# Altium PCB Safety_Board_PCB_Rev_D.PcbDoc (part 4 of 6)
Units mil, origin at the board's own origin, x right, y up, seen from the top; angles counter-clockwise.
Board outline 11000 x 4400 mil, 6 copper layers (L1-TOP, L2-Plane, L3-Signal, L4-Signal, L5-Plane, L6-BOT); 712 components, 540 nets, 2214 pads, 875 vias.
Unrouted connection lines stored in the file: 3.
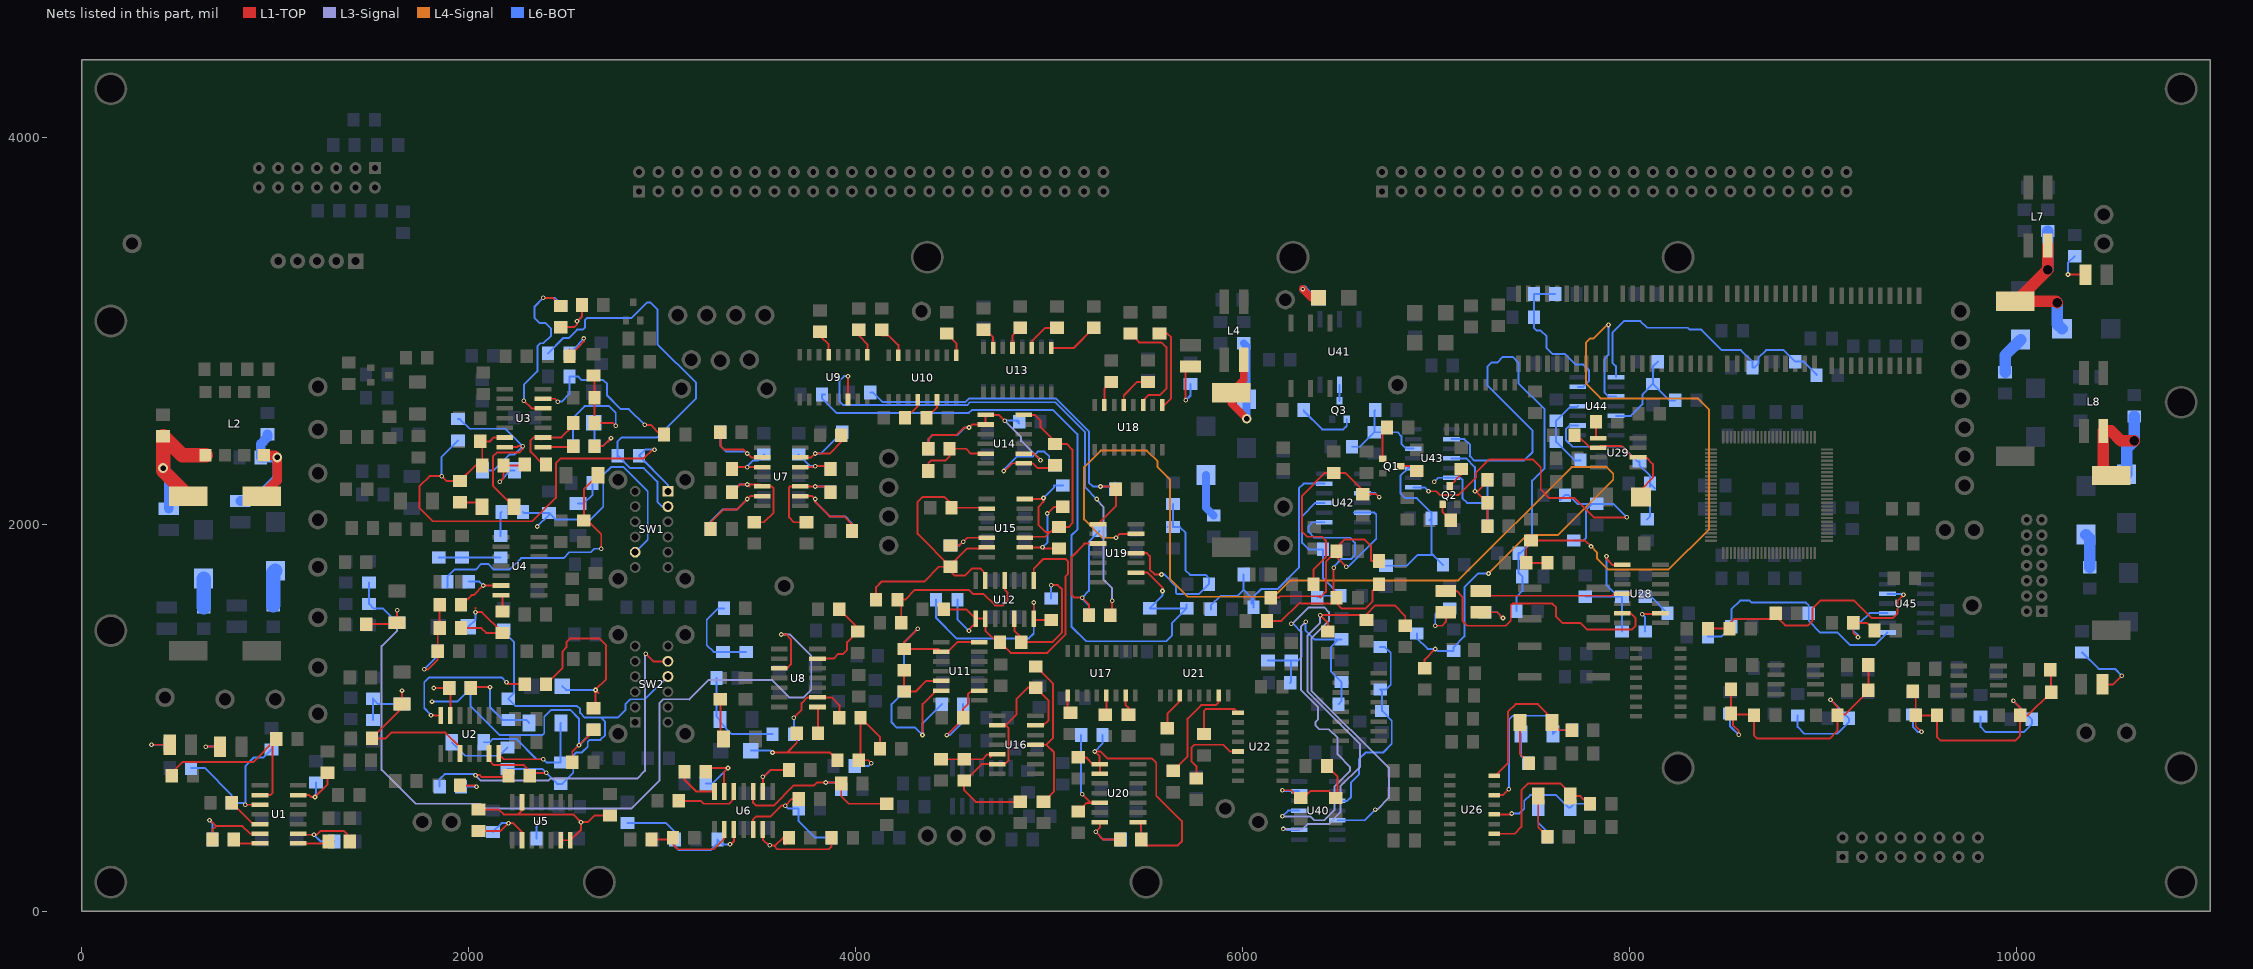
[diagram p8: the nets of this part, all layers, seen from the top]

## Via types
v1: diameter 24, hole 12, L1-TOP to L6-BOT, 720 vias
v2: diameter 50, hole 28, L1-TOP to L6-BOT, 138 vias
v3: diameter 28, hole 50, L1-TOP to L6-BOT, 17 vias

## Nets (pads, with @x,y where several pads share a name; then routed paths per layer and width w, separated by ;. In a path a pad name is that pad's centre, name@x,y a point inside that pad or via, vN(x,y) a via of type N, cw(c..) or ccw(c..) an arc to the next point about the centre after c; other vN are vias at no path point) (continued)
NetC28_2: C28.2 R130.1 R133.1 U40.13 | length 597.8
  L1-TOP w10: v1(6205,625) 6250,625 R130.1@6289.88,585.12 ; R130.1@6300,585.12 6315.12,585.12 6350,620 6445.12,620 R133.1@6480,585.12 6490,595.12 6490,695.12 C28.2@6435.12,750
  L6-BOT w10: v1(6205,625) 6205,630 6215,620 U40.13@6291.57,620
NetC29_2: C29.2 R131.1 R134.1 U42.3 | length 1184.4
  L1-TOP w10: R131.1@6365.12,1690 6365.12,1764.28 6430,1829.16 6430,1915 6410,1935 6334.04,1935 6307,1962.04 6307,2147 6424.88,2264.88 6530.12,2264.88 6620,2175 C29.2@6620,2155.12 6689.88,2155.12 v1(6705,2140)
  L6-BOT w10: U42.3@6618.43,2160 6685,2160 v1(6705,2140)
NetC30_2: C30.2 R126.1 R135.1 U42.5 | length 1446.8
  L1-TOP w10: R126.1@6145.12,1620 6185,1620 6192.66,1627.65 6407.66,1627.65 ; 6400,1620 6430,1650 6430,1805.12 R135.1@6484.88,1860 ; v1(6535,1780) 6484.88,1830.12 6484.88,1879.88 6525,1920 6630,1920 6662.43,1887.57 6662.43,1812.57 6665,1810 C30.2@6704.88,1810
  L6-BOT w10: v1(6535,1780) 6545,1780 6690,1925 6690,2050 6680,2060 6575,2060
NetC31_2: C31.2 R124.1 R136.1 U42.9 | length 1528.8
  L1-TOP w10: R124.1@6125.12,1500 6200,1500 6290,1590 6454.88,1590 R136.1@6484.88,1620 6470,1634.88 v1(6470,1775) ; R136.1@6470,1595 6485,1610 R136.1@6485,1645 ; R136.1@6484.88,1590.12 6510,1565 6635,1565 6670,1600 6670,1655.12 C31.2@6704.88,1690
  L6-BOT w10: U42.9@6421.57,2010 6360,2010 6340,1990 6340,1960 6370,1930 6555,1930 6580,1905 6580,1840 6560,1820 6510,1820 6470,1780 v1(6470,1775)
NetC32_2: C32.2 R137.1 R143.1 U40.9 | length 2301.1
  L1-TOP w10: R137.1@6440,1445.12 6440,1490 v1(6400,1530) 6615.12,1530 R143.1@6640,1505.12 6640,1535 6685,1580 6785,1580 6840,1525 C32.2@6840,1475.12
  L3-Signal w10: v1(6210,425) 6310,425 6335,450 6445,450 6505,510 6505,645 6605,745 6605,865 6335,1135 6335,1425 6400,1490 v1(6400,1530)
  L6-BOT w10: v1(6210,425) 6210,435 6225,420 U40.9@6291.57,420
NetC34_2: C34.2 R157.2 R158.1 U43.11 | length 555.6
  L1-TOP w10: v1(7200,2170) 7204.88,2170 C34.2@7264.88,2110 R158.1@7264.88,1990 ; 7215,2170 7264.88,2219.88 R157.2@7264.88,2230
  L6-BOT w10: U43.11@7078.43,2340 7155,2340 7200,2295 v1(7200,2170)
NetC35_2: C35.2 R156.1 R164.1 U44.3 | length 3423.3
  L1-TOP w10: R164.1@7574.88,1800 R156.1@7465.12,1800 7465.12,1890 C35.2@7490,1914.88 7770.12,1914.88 v1(7800,1885)
  L4-Signal w10: v1(7800,1885) 7830,1855 7830,1825 7890,1765 8200,1765 8410,1975 8410,2590.96 8350.96,2650 7850,2650 7775,2725 7775,2940 7795,2960 7813,2960 v1@7883,3030
  L3-Signal w10: v1@7890,3020 v1(7890,3030)
  L6-BOT w10: v1(7890,3030) 7890,2875 7870,2855 7870,2680 7890,2660 U44.3@7928.43,2660
NetC37_2: C37.2 U29.5 | length 93.4
  L1-TOP w10: C37.2@7824.88,2530 7824.88,2457.76 U29.5@7837.6,2445.04 U29.5@7839.84,2447.28
NetC38_1: C38.1 R162.1 U29.2 U29.6 | length 663
  L1-TOP w10: R162.1@7729.96,2460.04 7794.96,2395.04 U29.6@7837.6,2395.04 ; U29.6@7832.6,2390.04 7847.6,2405.04 7954.96,2405.04 8014.96,2345.04 8084.96,2345.04 8120,2310 8120,2240 8058.43,2178.43 C38.1@8058.43,2140
NetC40_2: C40.2 R170.1 R174.1 U45.5 | length 1404.1
  L1-TOP w10: C40.2@8405.12,1460 R170.1@8514.88,1460 8514.88,1484.88 8540,1510 8724.88,1510 R174.1@8754.88,1540 8754.88,1525.12 8803,1477 8922,1477 8945,1500 8945,1565 8985,1605 9160,1605 9250,1515 9360,1515 9385,1540 9385,1605 v1(9415,1635) v1@9415,1625
  L6-BOT w10: U45.5@9331.57,1640 9410,1640 v1(9415,1635)
NetC41_2: C41.2 C153.2 R171.2 R173.2 R175.2 R177.2 R178.2 R364.2 R369.1 | length 2065.8
  L1-TOP w10: R171.2@8522.85,1146.92 8522.85,1027.15 C41.2@8533.08,1016.92 ; v1(8562.96,911.92) 8562.96,931.92 8533.08,961.8 C41.2@8533.08,1016.92 ; v1(9037.96,1091.92) 9073.08,1056.8 9073.08,932.04 9032.96,891.92 8657.96,891.92 8642.85,907.04 8642.85,1016.92 C41.2@8533.08,1016.92 ; R175.2@9073.08,1016.92 9113.08,1016.92 9233.08,1136.92 R177.2@9233.08,1246.92
  L6-BOT w10: R364.2@8517.96,1021.8 8517.96,956.92 v1(8562.96,911.92) ; R369.1@8867.96,1011.8 8867.96,951.92 8902.96,916.92 9072.96,916.92 9133.08,977.04 C153.2@9133.08,996.92 9132.96,996.92 v1(9037.96,1091.92)
NetC42_2: C42.2 R176.1 R372.1 U45.3 | length 494.1
  L1-TOP w10: v1(9180,1415) 9155.12,1439.88 R176.1@9155.12,1490 9224.88,1490 C42.2@9264.88,1450
  L6-BOT w10: v1(9180,1415) 9180,1425 9155.12,1449.88 R372.1@9155.12,1490 9190,1490 9240,1540 U45.3@9331.57,1540
NetC43_2: C43.2 C160.2 R182.2 R184.2 R185.2 R186.2 R187.2 R378.2 R380.1 | length 2045.1
  L1-TOP w10: R182.2@9462.85,1136.92 9478.08,1121.68 9478.08,956.8 v1(9507.96,926.92) ; C43.2@9478.08,1011.92 R184.2@9587.85,1011.92 9587.85,902.04 9607.96,881.92 9992.96,881.92 10018.08,907.04 10018.08,1051.8 v1(9982.96,1086.92) ; R185.2@10018.08,1011.92 10058.08,1011.92 R187.2@10178.08,1131.92 10178.08,1241.92 R186.2@10173.08,1246.92
  L6-BOT w10: R378.2@9462.96,1016.8 9462.96,951.92 9487.96,926.92 v1(9507.96,926.92) ; R380.1@9812.96,1006.8 9812.96,951.92 9837.96,926.92 10037.96,926.92 10078.08,967.04 C160.2@10078.08,991.92 10077.96,991.92 v1(9982.96,1086.92)
NetC44_2: C44.2 L1.1 L2.1 R1.2 | length 846.7
  L1-TOP w75: L1.1@550,2145 420,2275 R1.2@420,2454.88 518.27,2356.61 L2.1@640,2356.61
  L6-BOT w50: v2(420,2290) 420,2275 450,2245 C44.2@450,2080.12
NetC46_2: C46.2 R190.1 | length 148.9
  L6-BOT w75: R190.1@630,1570.12 C46.2@630,1719.02
NetC47_2: C47.2 R189.2 R196.2 U1.3 | length 828.8
  L1-TOP w10: v1(845,550) U1.3@921.57,550
  L6-BOT w10: R189.2@565.12,740 635,740 775.12,599.88 C47.2@775.12,560 835,560 v1(845,550) 845,750 890,795 940.12,795 R196.2@980,834.88 R196.2@979.88,834.88
NetC48_2: C48.2 L2.4 L3.1 R193.2 R194.2 | length 888.9
  L1-TOP w50: L3.1@930,2145 1010,2225 v2(1010,2345) 998.39,2356.61 L2.4@940,2356.61
  L1-TOP w60: L3.1@930,2145 L3.1@940,2155
  L6-BOT w50: C48.2@820,2120.12 895.12,2120.12 1010,2235 v2(1010,2345) R193.2@925.12,2345 925.12,2415.12 960,2450 R194.2@960,2464.88
NetC50_1: C50.1 R195.1 | length 183
  L6-BOT w75: R195.1@990,1580.12 990,1749.02 C50.1@1000,1759.02
NetC61_2: C61.2 D3.K D15.A R14.2 R206.2 U8.3 | length 4962.2
  L1-TOP w10: R14.2@1469.76,1483.11 1622.32,1483.11 D3.K@1629.65,1490.43 1629.65,1554.65 v1(1630,1555) ; U8.3@3605,1255 3645,1255 3665,1275 3665,1405 3640,1430 v1(3615,1430)
  L3-Signal w7: 3005,1095 3140,1095
  L3-Signal w10: v1(1630,1555) 1630,1450 1550,1370 1550,730 1725,555 2060,555 2085,530 2840,530 2985,675 2985,1075 3005,1095 ; 3140,1095 3240,1195 3565,1195 3655,1105 3730,1105 3770,1145 3770,1320 3660,1430 v1(3615,1430)
  L6-BOT w10: R206.2@1484.65,1697.99 C61.2@1484.65,1588.23 1509.76,1563.11 1556.97,1563.11 D15.A@1629.65,1490.43 ; D15.A@1629.65,1474.65 D15.A@1629.65,1490.43 ; v1(1630,1555) 1630,1490.79 D15.A@1629.65,1490.43
NetC62_2: C62.2 D5.K D18.A R16.2 R209.1 U2.3 | length 1213.9
  L1-TOP w10: v1(1655,1140) 1654.65,1139.65 1654.65,1047.99 R16.2@1499.76,893.11 1569.65,893.11 1599.65,923.11 1879.65,923.11 1954.65,848.11 U2.3@1954.65,784.69
  L6-BOT w10: R209.1@1504.65,988.23 C62.2@1504.65,1097.99 1532.2,1070.43 D18.A@1654.65,1070.43 1655,1070.79 v1(1655,1140)
NetC63_1: C63.1 R25.2 | length 167.3
  L1-TOP w10: R25.2@1955.12,650 2032.76,650 v1(2039.65,643.11)
  L6-BOT w10: C63.1@1959.76,643.11 v1(2039.65,643.11)
NetC63_2: C63.2 R29.1 SW2.11 | length 2030.4
  L1-TOP w10: v1(2034.65,703.11) 2056.89,703.11 2067.59,692.41 2167.29,692.41 R29.1@2174.88,700 ; v1(2915,1330) 2953.78,1291.22 SW2.11@3029.29,1291.22
  L3-Signal w10: v1(2034.65,703.11) 2062.76,675 2411.66,675 2421.66,685 2870,685 2910,725 2910,1325 v1(2915,1330)
  L6-BOT w10: C63.2@1849.53,643.11 1849.53,682.99 1874.65,708.11 2029.65,708.11 v1(2034.65,703.11)
NetC64_1: C64.1 R19.2 R20.1 R21.1 R235.2 SW1.1 U3.6 | length 2824.6
  L1-TOP w10: U3.6@2186.22,2448.11 2129.65,2448.11 2109.65,2428.11 R19.2@2059.76,2428.11 2069.53,2418.35 R20.1@2069.53,2303.11 2034.53,2303.11 R21.1@1954.65,2223.23 1884.53,2223.23 v1(1859.65,2248.11) 1798.11,2248.11 1745,2195 1745,2085 1815,2015 2329.23,2015 2450,2135.77 2450,2315 2475,2340 2905,2340 2950,2385 v1(2960,2385)
  L6-BOT w10: v1(1859.65,2248.11) 1859.65,2347.99 C64.1@1944.65,2432.99 ; v1(2960,2385) 2911.65,2385 R235.2@2879.76,2353.11 3029.29,2203.58 SW1.1@3029.29,2169.96
NetC64_2: C64.2 D6.K D21.A U3.7 | length 1237.1
  L1-TOP w10: U3.7@2186.22,2398.11 2249.65,2398.11 2254.65,2403.11 v1(2279.65,2403.11) 2279.65,2389.65 2260,2370 2145,2370 2125,2350 2125,2197.68 D6.K@2232.68,2090
  L6-BOT w10: C64.2@1944.65,2543.23 1954.53,2543.23 2004.65,2493.11 2189.65,2493.11 v1(2279.65,2403.11) 2237.32,2360.79 2210.79,2360.79 2128.11,2278.11 D21.A@2071.97,2278.11
NetC65_1: C65.1 R222.2 | length 126.9
  L6-BOT w10: R222.2@2164.65,1938.23 2164.65,2058.23 C65.1@2169.53,2063.11
NetC65_2: C65.2 R228.1 SW1.11 | length 1357.9
  L6-BOT w10: C65.2@2279.76,2063.11 2284.88,2057.99 R228.1@2414.65,2057.99 ; v1(2354.65,1988.11) 2414.65,2048.11 R228.1@2414.65,2057.99 ; SW1.11@2860,1855 2925,1920 2925,2170 2800,2295 2735,2295 2695,2255 2695,2090 2630,2025 2447.64,2025 R228.1@2414.65,2057.99
NetC66_2: C66.2 R211.2 R222.1 | length 320
  L6-BOT w10: R211.2@1844.65,1827.99 R222.1@2164.65,1827.99
NetC69_1: C69.1 R34.2 | length 286.3
  L1-TOP w10: R34.2@2519.76,2903.23 R34.2@2519.76,2868.11 2570,2918.35 2570,2920 2595,2945 v1(2595,2960)
  L6-BOT w10: C69.1@2519.76,2903.23 C69.1@2519.76,2883.11 2570,2933.35 2570,2935 v1(2595,2960)
NetC69_2: C69.2 R235.1 SW1.2 | length 2271.7
  L6-BOT w10: C69.2@2409.53,2883.11 2489.53,2963.11 2518.11,2963.11 2560,3005 2590,3005 2600,3015 2600,3055 2610,3065 2840,3065 2920,3145 2940,3145 2975,3110 2975,2930 3175,2730 3175,2650 2973.11,2448.11 2789.65,2448.11 2769.53,2427.99 R235.1@2769.53,2338.23 ; R235.1@2769.53,2353.11 2771.89,2353.11 2835,2290 2905,2290 2975,2220 2975,2115 2998.78,2091.22 SW1.2@3029.29,2091.22
NetC73_1: C73.1 R29.2 R220.1 R223.1 R224.1 SW2.10 U2.6 | length 2563.3
  L1-TOP w10: U2.6@2104.65,814.69 2104.65,780.35 2130,755 2285,755 2315.12,724.88 R29.2@2315.12,700 2330.12,715 v1(2400,715)
  L6-BOT w7: 2835,1095 2910,1095
  L6-BOT w10: R220.1@2180,1454.88 2180,1445 2232.65,1392.35 2232.65,1126.23 R223.1@2204.65,1098.23 2242.87,1060 2560,1060 2575,1045 2575,1025 2600,1000 2770,1000 2810.85,1040.85 2810.85,1070.85 2835,1095 ; R224.1@2200,734.88 2380.12,734.88 2457.01,657.99 2482.99,657.99 2540,715 2540,805 2555,820 2585,820 2615,850 2615,875 2625,885 2680,885 2705,910 2705,980 2685,1000 ; 2910,1095 3027.48,1212.48 SW2.10@3029.29,1212.48
NetC73_2: C73.2 D20.A D23.K U2.7 | length 905.9
  L1-TOP w10: U2.7@2154.65,814.69 2154.65,810.35 2180,785 v1(2385,785)
  L6-BOT w10: D20.A@2077.32,873.11 2108.11,873.11 2125,890 2245,890 2350,785 v1(2385,785) 2401.77,768.23 C73.2@2474.65,768.23 2474.65,970.43 D23.K@2477.32,973.11
NetC78_2: C78.2 R237.2 R239.2 U6.3 | length 764.4
  L1-TOP w10: v1(3350,345) 3355,345 3370,360 U6.3@3370,421.57
  L6-BOT w10: R237.2@2820,454.88 3020.12,454.88 3065.12,409.88 3065.12,334.88 3085,315 3250,315 3285.12,350.12 C78.2@3285.12,370 3310.12,345 v1(3350,345)
NetC79_2: C79.2 R54.2 R247.2 U7.3 | length 359.4
  L1-TOP w10: R54.2@3360.12,2285 3370.12,2295 v1(3440,2295) U7.3@3516.57,2295
  L6-BOT w10: C79.2@3360.12,2285 3370.12,2295 v1(3440,2295) 3440,2300 3470,2330 3495.12,2330 R247.2@3525,2359.88
NetC80_2: C80.2 R55.2 R58.2 U7.5 | length 596
  L1-TOP w10: R55.2@3360.12,2165 3400.12,2205 3506.57,2205 U7.5@3516.57,2195 3565,2195 3575,2185 3575,2060 3525.12,2010.12 R58.2@3475,2010.12 ; v1(3440,2205) 3450,2195
  L6-BOT w10: C80.2@3360.12,2165 3400.12,2205 v1(3440,2205)
NetC82_2: C82.2 R245.1 R246.2 | length 461.1
  L6-BOT w10: R245.1@3318.31,1565 3290,1565 3230,1505 3230,1375 3265.12,1339.88 C82.2@3433.43,1339.88
NetC86_2: C86.2 R63.2 R252.2 U6.5 | length 678
  L1-TOP w10: U6.5@3470,421.57 3470,475 3485,490 3560,490 3615,545 v1(3635,545) 3670,580 R63.2@3704.88,580
  L6-BOT w10: v1(3635,545) 3650,530 C86.2@3704.88,530 3704.88,465.12 3790,380 R252.2@3874.88,380
NetC88_2: C88.2 R67.2 R248.2 U7.12 | length 360.6
  L1-TOP w10: U7.12@3713.43,2295 3785,2295 v1(3790,2300) 3850,2300 3865,2285 R67.2@3869.88,2285
  L6-BOT w10: R248.2@3705,2359.88 3764.88,2300 3854.88,2300 C88.2@3869.88,2285
NetC89_2: C89.2 R61.2 R68.2 U7.10 | length 577
  L1-TOP w10: R61.2@3745,2010.12 3679.88,2010.12 3655,2035 3655,2190 3660,2195 v1(3790,2195) 3839.88,2195 R68.2@3869.88,2165
  L6-BOT w10: v1(3790,2195) 3839.88,2195 C89.2@3869.88,2165
NetC90_2: C90.2 R76.2 R81.2 U6.10 | length 982.2
  L1-TOP w10: U6.10@3470,618.43 3470,560 3485,545 3575,545 3680,650 3785,650 3800,665 3919.88,665 R76.2@3924.88,660 3924.88,595.12 3964.88,555.12 R81.2@4160,555.12
  L6-BOT w10: v1(3845,665) 3889.88,665 C90.2@3924.88,630
NetC104_2: C104.2 R113.1 R261.1 U19.1 | length 1981.9
  L1-TOP w10: U19.1@5251.57,2000 5344.88,2093.31 R113.1@5344.88,2180 5329.88,2195 v1(5265,2195)
  L6-BOT w10: R261.1@4075.12,2680 4090,2680 4138,2632 4567.96,2632 4585.96,2650 5035,2650 5035,2649.04 5205,2479.04 5205,2215 5225,2195 5325,2195 C104.2@5340,2180 C104.2@5340,2215
NetC105_2: C105.2 R109.1 R287.1 U19.3 | length 1015.9
  L1-TOP w10: R109.1@5204.88,1530 5204.88,1585.12 v1(5170,1620) 5130,1620 5115,1635 5115,1830 5180,1895 5180,1900 U19.3@5251.57,1900
  L6-BOT w10: R287.1@5204.88,1530 5204.88,1580.12 5170,1615 v1(5170,1620) 5204.88,1654.88 5204.88,1909.88 C105.2@5260,1965
NetC108_2: C108.2 R298.1 R300.1 U19.11 | length 1104.9
  L1-TOP w10: U19.11@5448.43,1850 5505,1850 5520,1835 5520,1765 5545,1740 v1(5580,1740)
  L6-BOT w10: v1(5580,1740) 5595,1740 5655,1680 5655,1645 5660,1640 5775,1640 5825,1690 R300.1@5825.12,1690 5825.12,1719.88 5807.57,1737.43 5727.57,1737.43 5705,1760 5705,1955 5674.88,1985.12 C108.2@5640,1985.12 R298.1@5640,2104.88 ; C108.2@5610,1985 C108.2@5610,1985.12
NetC109_2: C109.2 R250.1 R295.1 U19.9 | length 3706.2
  L1-TOP w10: U19.9@5448.43,1750 5508,1750 5585,1673 v1(5585,1655)
  L6-BOT w10: R250.1@3840,2670 R250.1@3825.12,2670 3825.12,2649.88 3900,2575 4585,2575 4600,2590 5020,2590 5145,2465 5145,1971.66 5115,1941.66 5115,1470 5190,1395 5605,1395 5635,1425 5635,1490.12 C109.2@5710,1565.12 ; v1@5590,1650 v1(5585,1655) 5585,1630.12 R295.1@5520,1565.12 C109.2@5710,1565.12 ; C109.2@5710,1585 C109.2@5710,1565.12
NetC110_1: C110.1 R302.1 | length 225.5
  L6-BOT w40: C110.1@5810,2254.02 5810,2085.12 R302.1@5850,2045.12
NetC113_1: C113.1 L4.4 L5.1 R307.2 | length 761.2
  L1-TOP w40: L4.4@6005,2850 6005,2745 L5.1@5940,2680 5940,2625 v2(6020,2545)
  L6-BOT w40: R307.2@6005,2934.88 6020,2919.88 v2(6020,2545)
NetC114_2: C114.2 R303.1 R308.1 U42.13 | length 1293.8
  L6-BOT w10: R303.1@5834.88,1560 5834.88,1579.88 5885.12,1630.12 5974.88,1630.12 6004.88,1660.12 ; R308.1@6004.88,1740 6004.88,1660.12 ; C114.2@6045,1590 6045,1620 6004.88,1660.12 ; C114.2@6054.88,1570 6054.88,1624.88 6095,1665 6180,1665 6290,1775 6290,2185 6315,2210 U42.13@6421.57,2210
NetC115_2: C115.2 R309.1 R312.1 U40.5 | length 2228.7
  L3-Signal w10: v1(6250,1485) 6250,1480 6340,1570 6420,1570 6445,1545 6445,1500 6355,1410 6355,1140 6755,740 6755,585 6695,525 v1(6685,525)
  L6-BOT w10: C115.2@6130,1294.88 6284.88,1294.88 6305,1315 6305,1440 6260,1485 v1(6250,1485) ; R309.1@6245.12,1180 6250,1184.88 R312.1@6250,1294.88 ; 6300,1445 6305,1445 ; U40.5@6488.43,470 6630,470 v1(6685,525)
NetC117_2: C117.2 R314.1 R316.1 U42.11 | length 804.5
  L6-BOT w10: C117.2@6385.12,1620 6395.12,1630 R316.1@6504.88,1630 6414.88,1720 R314.1@6414.88,1870 6340,1870 6307,1903 6307,2042 6375,2110 U42.11@6421.57,2110
NetC119_2: C119.2 R313.1 R317.1 U40.11 | length 2189.9
  L3-Signal w10: v1(6205,490) 6350,490 6370,470 6420,470 6475,525 6475,645 6555,725 6555,745 6490,810 6490,895 6445,940 6395,940 6375,960 6375,977 6390,992 6390,1055 6300,1145 6300,1470 v1(6325,1495)
  L6-BOT w10: v1(6205,490) 6235,520 U40.11@6291.57,520 ; v1(6325,1495) 6325,1450 6370.12,1404.88 R317.1@6510,1404.88 ; R317.1@6494.88,1404.88 6455,1365 6455,1239.88 C119.2@6510,1184.88 6510,1084.88 R313.1@6495.12,1070
NetC121_2: C121.2 R315.1 R322.1 U43.5 | length 523.2
  L6-BOT w10: R315.1@6565.12,2400 6604.88,2400 R322.1@6680,2475.12 ; C121.2@6684.88,2590 6680,2585.12 R322.1@6680,2475.12 ; U43.5@6881.57,2390 6845,2390 6820,2415 6820,2455 6799.88,2475.12 R322.1@6680,2475.12
NetC122_2: C122.2 R324.1 R325.1 U40.3 | length 1097.1
  L6-BOT w10: U40.3@6488.43,570 6540,570 6560,590 6560,665 6601.87,706.87 6601.87,786.87 6635,820 6725,820 6770,865 6770,985 6720,1035 6720,1134.88 C122.2@6710,1144.88 6739.88,1144.88 6765,1170 6765,1335 6735.12,1364.88 R324.1@6710,1364.88
NetC124_2: C124.2 R323.1 R326.1 U43.3 | length 951.1
  L6-BOT w10: R323.1@6740,1785.12 6848,1785.12 6902.88,1840 6984.88,1840 ; U43.3@6881.57,2290 6855,2290 6815,2250 6815,2160 6840,2135 6900,2135 6975.12,2059.88 6975.12,1849.76 C124.2@7034.88,1790 ; R326.1@6965.12,2020 R326.1@6975.12,2030
NetC125_2: C125.2 R147.1 R328.1 U19.13 | length 6027.6
  L1-TOP w10: v1(5345,1930) 5365,1950 U19.13@5448.43,1950 ; R147.1@6940,1255.12 6940,1300 v1(6995,1355)
  L4-Signal w10: v1(5345,1930) 5275,1930 5180,2025 5180,2295 5265,2380 5505,2380 5560,2325 5560,2295 5623,2232 5623,1717 5715,1625 6160.96,1625 6245.96,1710 7115,1710 7700,2295 7880,2295 7915,2260 7915,2230 7630,1945 7470,1945 v1(7270,1745)
  L6-BOT w10: R328.1@6900,1434.88 6900,1410 6955,1355 v1(6995,1355) 7005.12,1344.88 C125.2@7090,1344.88 7090,1365 7145,1420 7145,1675 7215,1745 v1(7270,1745)
NetC126_2: C126.2 R339.2 R340.1 U43.13 | length 659.2
  L6-BOT w10: v1(6990,2220) 7010,2240 U43.13@7078.43,2240 ; U43.13@7105,2240 U43.13@7078.43,2240 ; R340.1@7264.88,1990 R339.2@7264.88,2230 ; C126.2@7264.88,2110 7160,2110 7135,2135 7135,2230 7125,2240 U43.13@7078.43,2240
NetC127_2: C127.2 R341.1 R342.1 U43.9 | length 2673
  L6-BOT w10: U43.9@7078.43,2440 7145,2440 7175,2410 7175,2350 7195,2330 7455,2330 7498,2373 7498,2482.96 7265,2715.96 7265,2815 7285,2835 7315,2835 7345,2865 7395,2865 7425,2835 7425,2729.04 7560,2594.04 7560,2290 7495,2225 7495,1909.88 7435.12,1850 R341.1@7425.12,1850 7425.12,1749.76 R342.1@7444.88,1730 7444.88,1654.88 7414.88,1624.88 C127.2@7414.88,1550
NetC129_2: C129.2 R337.1 R338.1 U44.13 | length 821.9
  L6-BOT w10: C129.2@7614.88,3190 R337.1@7505.12,3190 7505.04,3070 7505,3015 7520,3000 7540,3000 7570,2970 7570,2910 7600,2880 7665,2880 7720,2825 7760,2825 7790,2795 7790,2740 7760,2710 U44.13@7731.57,2710
NetC130_2: C130.2 R347.1 R354.1 U43.1 | length 2065
  L1-TOP w10: v1(6960,2170) 7000,2170 7020,2150 7115,2150 7205,2240 7205,2265 7275,2335 7500,2335 7540,2295 7540,2180 7585,2135 7715,2135 7815,2035 v1(7985,2035)
  L6-BOT w10: U43.1@6881.57,2190 6940,2190 v1(6960,2170) ; C130.2@7640,2124.88 C130.2@7665.12,2150 7685,2150 7729.88,2105.12 7914.88,2105.12 v1(7985,2035) ; R347.1@7709.88,1915 R347.1@7710,1914.88 7759.88,1914.88 7775,1930 7775,2075 R354.1@7805.12,2105.12
NetC131_2: C131.2 R355.1 R356.1 U28.1 | length 713.8
  L1-TOP w10: v1(7880,1835) 7880,1820 7910,1790 U28.1@7961.57,1790
  L6-BOT w10: C131.2@7770,1624.88 R355.1@7960,1624.88 R356.1@7960,1445.12 ; v1(7880,1835) 7880,1685 R355.1@7940.12,1624.88
NetC132_2: C132.2 R345.1 R346.1 U44.11 | length 416.7
  L6-BOT w10: U44.11@7731.57,2610 7726.46,2604.88 7690,2604.88 R345.1@7620,2534.88 R346.1@7620,2425.12 7715.12,2330 C132.2@7744.88,2330
NetC133_2: C133.2 R357.1 R358.1 U44.9 | length 914.5
  L6-BOT w10: U44.9@7731.57,2510 7690,2510 7670,2490 7670,2435 7705,2400 7965,2400 8040.12,2324.88 R357.1@8050,2324.88 8050,2305 8105.12,2249.88 8105.12,2040.24 R358.1@8090,2025.12 ; C133.2@8105.12,2210 C133.2@8130,2185.12
NetC135_2: C135.2 R359.1 R360.1 U44.5 | length 565.3
  L6-BOT w10: U44.5@7928.43,2560 8005.96,2560 8065,2619.04 8065,2670.12 R360.1@8120,2725.12 ; R359.1@8145.12,2840 8120,2814.88 R360.1@8120,2725.12 ; C135.2@8234.88,2640 8205.12,2640 R360.1@8120,2725.12
NetC136_2: C136.2 R361.1 R362.1 U28.9 | length 473.6
  L1-TOP w10: v1(8065,1535) 8153.43,1535 U28.9@8158.43,1540
  L6-BOT w10: R362.1@8080,1445.12 8080,1520 v1(8065,1535) 8189.88,1535 C136.2@8194.88,1540 8110,1624.88 R361.1@8080,1624.88
NetC141_2: C141.2 R365.1 R368.1 U45.1 | length 1224.8
  L6-BOT w10: C141.2@8405.12,1420 8474.88,1420 R365.1@8524.88,1470 8524.88,1559.88 8570,1605 8620,1605 8630,1595 8910,1595 8925.12,1579.88 8925.12,1499.88 8985,1440 9075,1440 9140,1375 9266.57,1375 U45.1@9331.57,1440
NetC144_2: C144.2 R367.1 R371.1 U44.1 | length 1546
  L6-BOT w10: U44.1@7928.43,2760 7928.43,2816.57 7910,2835 7910,2990 7970,3050 8055,3050 8090,3015 8300,3015 8310,3005 8370,3005 8475,2900 8575,2900 8635.12,2839.88 C144.2@8635.12,2810 8645,2810 8665,2830 8665,2860 8705,2900 8795.12,2900 R367.1@8855.12,2840 8900,2840 8964.88,2775.12 R371.1@8964.88,2770
NetC157_1: C157.1 R382.1 | length 202
  L6-BOT w60: R382.1@9940,2785.12 9940,2874.02 C157.1@10020,2954.02
NetC161_1: C161.1 L6.1 L7.4 R386.2 | length 920.4
  L1-TOP w60: L6.1@9992.96,3151.92 10203.08,3151.92 v3(10210,3145) ; L6.1@9996.92,3151.92 v3(10160,3315) L7.4@10160,3440
  L6-BOT w60: v3(10160,3315) R386.2@10160,3514.88 ; v3(10210,3145) 10210,3034.02 C161.1@10234.02,3010
NetC163_1: C163.1 R389.1 | length 177.2
  L6-BOT w60: C163.1@10357.96,1945.93 10377.96,1925.93 R389.1@10377.96,1777.04
NetC164_1: C164.1 L8.4 L9.1 R391.2 | length 742.7
  L1-TOP w60: L9.1@10487.96,2251.92 10447.96,2291.92 L8.4@10447.96,2481.92 10487.96,2481.92 10537.96,2431.92 v3(10607.96,2431.92)
  L6-BOT w60: C164.1@10567.96,2257.9 10567.96,2391.92 v3(10607.96,2431.92) R391.2@10607.96,2556.8
NetD6_A: D6.A R21.2 | length 122.2
  L1-TOP w10: R21.2@1954.65,2112.99 2044.33,2112.99 D6.A@2067.32,2090
NetD7_A: D7.A R41.2 R214.1 | length 1394.8
  L1-TOP w10: D7.A@2667.32,2253.11 2594.65,2180.43 R41.2@2594.65,2018.23 2614.53,2018.23 2684.65,1948.11 v1(2684.65,1873.11)
  L6-BOT w10: R214.1@1889.53,1673.23 1889.53,1729.53 1925,1765 2035,1765 2065,1795 2100,1795 2130,1765 2210,1765 2270,1825 2490,1825 2520,1855 2630,1855 2648.11,1873.11 v1(2684.65,1873.11)
NetD9_A: D9.A R52.2 | length 212.1
  L1-TOP w10: R52.2@3300,1094.88 3300,907.32 D9.A@3317.32,890
NetD10_K: D10.K D28.A | length 200.3
  L1-TOP w40: v1(6310,3215) 6355,3170 D10.K@6391.5,3170
  L6-BOT w40: v1(6310,3215) 6315,3215 6360,3170 D28.A@6391.5,3170
NetD13_A: D13.A R165.2 U26.8 | length 777.2
  L1-TOP w10: U26.8@7300.16,700 7305,700 7370,765 7370,1030 7410,1070 7525,1070 7597.68,997.32 D13.A@7597.68,975 7637.68,935 R165.2@7699.88,935
NetD13_K: D13.K R159.1 | length 229.7
  L1-TOP w10: D13.K@7432.32,975 7432.32,812.68 7479.88,765.12 R159.1@7479.88,765
NetD14_A: D14.A R167.2 U26.2 | length 764.4
  L1-TOP w10: U26.2@7300.16,400 7405,400 7440,435 7440,625 7475,660 7640,660 7692.68,607.32 D14.A@7692.68,595 7745,595 7785,555 R167.2@7794.88,555
NetD14_K: D14.K R160.1 | length 229.7
  L1-TOP w10: D14.K@7527.32,595 7527.32,432.56 R160.1@7574.88,385
NetD19_K: D19.K R22.2 R28.2 | length 504.4
  L1-TOP w10: R22.2@1959.76,1463.11 2064.65,1463.11 2089.76,1437.99 R28.2@2174.65,1437.99 2067.64,1545 v1(2035,1545) ; 2034.65,1563.11 2034.65,1568.11
  L6-BOT w10: D19.K@1998.5,1470 2035,1506.5 v1(2035,1545)
NetD20_K: D20.K R224.2 | length 334.4
  L6-BOT w10: D20.K@1911.97,873.11 1981.97,803.11 2157.99,803.11 R224.2@2200,845.12
NetD21_K: D21.K R20.2 R30.1 | length 304.5
  L1-TOP w10: v1(2160,2220) 2179.76,2239.76 R20.2@2179.76,2303.11 2284.53,2303.11 R30.1@2289.53,2308.11
  L6-BOT w10: v1(2160,2220) 2218.11,2278.11 D21.K@2237.32,2278.11
NetD22_K: D22.K R32.2 R42.2 | length 1052.8
  L1-TOP w10: R32.2@2399.76,1173.11 2484.65,1257.99 2484.65,1343.11 2505,1363.46 2505,1390 2525,1410 2675,1410 2709.65,1375.35 2709.65,1198.11 v1(2654.65,1143.11) ; R42.2@2644.65,1048.23 2654.65,1058.23 v1(2654.65,1143.11) ; v1@2654.65,1153.11 v1(2654.65,1143.11) ; 2669.65,1128.11 v1(2654.65,1143.11)
  L6-BOT w10: D22.K@2483.15,1163.11 2503.15,1143.11 v1(2654.65,1143.11)
NetD23_A: D23.A R24.1 R223.2 | length 442.4
  L1-TOP w10: R24.1@2009.76,1153.11 2014.76,1158.11 v1(2109.65,1158.11)
  L6-BOT w10: v1(2109.65,1158.11) 2109.65,1053.11 2174.76,987.99 2297.09,987.99 D23.A@2311.97,973.11
NetD24_K: D24.K R40.2 R229.2 | length 328.8
  L1-TOP w10: R40.2@2649.76,2403.11 2693.11,2403.11 v1(2735,2445)
  L6-BOT w10: D24.K@2644.65,2524.61 2649.76,2519.49 R229.2@2649.76,2403.11 2693.11,2403.11 v1(2735,2445)
NetD25_K: D25.K R232.2 | length 154.7
  L6-BOT w10: D25.K@2564.65,2105.79 2592.32,2105.79 2639.76,2153.23 R232.2@2639.76,2213.11
NetD26_K: D26.K R62.2 R71.2 | length 587.9
  L1-TOP w10: v1(3570,820) 3864.88,820 R71.2@3904.88,780 ; 3644.76,820 3694.88,870.12 R62.2@3694.88,920
  L6-BOT w10: D26.K@3458.5,830 3560,830 v1(3570,820)
NetD27_K: D27.K R242.2 R249.1 | length 533.1
  L6-BOT w10: R242.2@3279.88,1205 3279.88,1007.44 D27.K@3297.32,990 3297.32,977.68 3360,915 R249.1@3569.88,915
NetD29_A: D29.A R350.2 U26.6 | length 869.6
  L1-TOP w10: U26.6@7300.16,600 7345,600 v1(7375,630)
  L6-BOT w10: v1(7375,630) 7375,990 7395,1010 7570,1010 7602.68,977.32 D29.A@7602.68,915 7622.68,935 R350.2@7704.88,935
NetD29_K: D29.K R343.1 | length 165.6
  L6-BOT w10: D29.K@7437.32,915 7437.32,802.56 R343.1@7474.88,765
NetD30_A: D30.A R352.2 U26.4 | length 594.8
  L1-TOP w10: U26.4@7300.16,500 7385,500 v1(7390,505)
  L6-BOT w10: v1(7390,505) 7430,505 7455,530 7455,570 7485,600 7620,600 7685,535 D30.A@7692.68,535 7712.68,555 R352.2@7794.88,555
NetD30_K: D30.K R344.1 | length 169.7
  L6-BOT w10: D30.K@7527.32,535 7527.32,457.68 7574.88,410.12 R344.1@7574.88,385
NetDS1_A: DS1.A R188.2 | length 189.8
  L1-TOP w10: v1(360,860) DS1.A@454.88,860
  L6-BOT w10: v1(360,860) R188.2@454.88,860
NetDS2_K: DS2.K R191.2 | length 149.8
  L1-TOP w10: v1(640,850) DS2.K@714.88,850
  L6-BOT w10: v1(640,850) R191.2@714.88,850
NetDS3_K: DS3.K R301.2 | length 285.5
  L1-TOP w10: v1(5705,2640) 5705,2789.88 DS3.K@5730,2814.88
  L6-BOT w10: v1(5705,2640) 5730,2665 R301.2@5730,2724.88 ; v1@5705,2650 5705,2655
NetDS4_A: DS4.A R334.1 | length 260.5
  L1-TOP w10: v1(6995,1475) 7030,1475 7050,1495 DS4.A@7050,1544.88
  L6-BOT w10: v1(6995,1475) 6995,1535 7024.88,1564.88 R334.1@7070,1564.88
NetDS4_K: DS4.K U28.6 | length 1433.6
  L1-TOP w10: DS4.K@7050,1655.12 7104.88,1655.12 7135,1625 7135,1500 7160,1475 7360,1475 7385,1500 7385,1580 7395,1590 7600,1590 7620,1570 7620,1521.66 7651.66,1490 7745,1490 7780,1455 8010,1455 8030,1475 8030,1515 8005,1540 U28.6@7961.57,1540
NetDS5_A: DS5.A R336.1 | length 234.8
  L1-TOP w10: DS5.A@7230,1544.88 7315.12,1544.88 v1(7345,1515)
  L6-BOT w10: R336.1@7250,1544.88 7315.12,1544.88 v1(7345,1515)
NetDS5_K: DS5.K U28.4 | length 746.1
  L1-TOP w10: DS5.K@7230,1655.12 7255.12,1630 7910,1630 7920,1640 U28.4@7961.57,1640
NetDS6_K: DS6.K R387.2 | length 199.3
  L1-TOP w10: v1(10265,3290) DS6.K@10354.88,3290
  L6-BOT w10: v1(10265,3290) 10265,3349.88 R387.2@10300,3384.88
NetDS7_K: DS7.K R390.2 | length 373.2
  L1-TOP w10: DS7.K@10443.08,1171.92 10497.96,1171.92 v1(10542.96,1216.92)
  L6-BOT w10: R390.2@10337.96,1336.8 10422.85,1251.92 10507.96,1251.92 v1(10542.96,1216.92)
NetQ1_1: Q1.1 R144.1 | length 171.8
  L1-TOP w10: Q1.1@6722.76,2337.4 6722.76,2477.87 R144.1@6744.88,2500
NetQ1_3: Q1.3 R145.2 | length 93.2
  L1-TOP w10: Q1.3@6817.24,2300 6874.88,2300 R145.2@6900,2274.88
NetQ2_1: Q2.1 R150.1 | length 100.4
  L1-TOP w10: Q2.1@7032.6,2102.76 7032.6,2062.4 7075,2020 R150.1@7075.12,2020
NetQ2_3: Q2.3 R152.2 | length 114.9
  L1-TOP w10: Q2.3@7070,2197.24 7130,2257.24 R152.2@7130,2284.88 ; R152.2@7147.64,2274.88 R152.2@7150,2274.88
NetQ3_1: Q3.1 R311.1 | length 309.3
  L6-BOT w10: R311.1@6315.12,2590 6315.12,2584.88 6410,2490 6520,2490 6537.4,2507.4 Q3.1@6537.4,2542.76
NetQ3_3: Q3.3 U41.2 | length 83.5
  L6-BOT w10: Q3.3@6500,2637.24 U41.2@6500,2720.71
NetR2_1: R2.1 R5.2 U1.2 | length 955.1
  L1-TOP w10: R2.1@464.88,700 464.88,714.88 520,770 884.88,770 R5.2@1004.88,890 ; U1.2@921.57,600 975,600 985,610 R5.2@985,870.12
NetR3_2: R3.2 U1.5 | length 192
  L1-TOP w10: R3.2@775.12,560 885.12,450 U1.5@921.57,450
NetR4_1: R4.1 R192.2 U1.6 | length 475.1
  L1-TOP w10: v1(660,470) 665,470 695,440 ; R4.1@674.88,370 674.88,419.88 695,440 ; U1.6@921.57,400 870,400 830,440 695,440
  L6-BOT w10: v1(660,470) 674.88,455.12 R192.2@674.88,370
NetR4_2: R4.2 U1.7 | length 144.7
  L1-TOP w10: R4.2@785.12,370 805.12,350 U1.7@921.57,350
NetR6_1: R6.1 R199.2 U1.13 | length 319.5
  L1-TOP w10: U1.13@1118.43,600 1175,600 1185,590 v1(1205,590) 1270,655 R6.1@1270,714.88
  L6-BOT w10: v1(1205,590) 1210,595 R199.2@1210,664.88
NetR8_1: R8.1 R201.2 U1.9 | length 433.8
  L1-TOP w10: U1.9@1118.43,400 1123.43,395 1215,395 1235,415 1355,415 1385.12,384.88 R8.1@1385.12,360
  L6-BOT w10: v1(1200,395) 1235,360 R201.2@1304.88,360
NetR8_2: R8.2 U1.8 | length 160.6
  L1-TOP w10: U1.8@1118.43,350 1264.88,350 R8.2@1274.88,360
NetR18_1: R18.1 R214.2 U4.6 | length 331
  L1-TOP w10: R18.1@1959.76,1583.11 1964.65,1583.11 2014.65,1633.11 2024.65,1633.11 v1(2074.65,1683.11) U4.6@2166.22,1683.11
  L6-BOT w10: R214.2@1999.76,1703.11 2054.65,1703.11 v1(2074.65,1683.11)
NetR18_2: R18.2 R22.1 R23.2 R215.1 | length 499.7
  L1-TOP w10: v1(1770,1250) 1790,1250 1839.53,1299.53 1839.53,1453.11 R22.1@1849.53,1463.11 R18.2@1849.53,1583.11
  L6-BOT w10: v1(1770,1250) 1839.53,1319.53 R215.1@1839.53,1343.11
NetR24_2: R24.2 R216.1 U2.13 | length 310.7
  L1-TOP w10: v1(1819.65,1153.11) R24.2@1899.53,1153.11 ; U2.13@1904.65,1011.54 R24.2@1904.65,1147.99 ; R24.2@1899.53,1153.11 R24.2@1904.65,1147.99 ; R24.2@1899.53,1153.11 R24.2@1904.65,1147.99
  L6-BOT w10: v1(1819.65,1153.11) R216.1@1899.53,1153.11
NetR27_1: R27.1 R221.2 U5.9 | length 402.4
  L1-TOP w10: R27.1@2050,414.88 2164.88,414.88 v1(2205,455) 2230,455 2275,410 U5.9@2275,366.57
  L6-BOT w10: R221.2@2125,409.88 2170.12,455 v1(2205,455)
NetR27_2: R27.2 R47.1 R217.2 U5.6 U5.13 U5.14 | length 1090.5
  L1-TOP w10: R27.2@2050,525.12 2154.88,525.12 2180,500 2540,500 v1(2580,460) ; 2255,500 2275,520 U5.6@2275,563.43 ; v1(2365,460) 2365,500 ; U5.13@2475,366.57 U5.14@2525,366.57 2580,421.57 v1(2580,460) ; R47.1@2730,494.88 2649.88,494.88 2615,460 v1(2580,460)
  L6-BOT w10: R217.2@2350.12,375 2350.12,445.12 v1(2365,460)
NetR28_1: R28.1 U4.7 | length 88.4
  L1-TOP w10: U4.7@2166.22,1633.11 2174.65,1624.69 R28.1@2174.65,1548.23
NetR30_2: R30.2 R39.1 U3.9 | length 446.3
  L1-TOP w10: U3.9@2373.07,2438.11 U3.9@2383.07,2448.11 ; R30.2@2399.76,2308.11 2384.65,2308.11 2319.65,2373.11 2319.65,2433.11 2334.65,2448.11 2478.11,2448.11 2539.53,2509.53 R39.1@2539.53,2523.11
NetR32_1: R32.1 U2.14 | length 779.6
  L1-TOP w10: v1(1804.65,1013.11) 1806.22,1011.54 U2.14@1854.65,1011.54 ; v1(2194.65,1183.11) 2204.65,1173.11 R32.1@2289.53,1173.11
  L6-BOT w10: v1(1804.65,1013.11) 1804.65,1015.35 1770,1050 1770,1183.46 1794.65,1208.11 2169.65,1208.11 v1(2194.65,1183.11)
NetR33_1: R33.1 R35.1 R231.2 | length 303.6
  L1-TOP w10: R33.1@2479.41,3013.23 R33.1@2474.65,3017.99 2544.53,3017.99 2559.65,3033.11 v1(2559.65,3048.11) 2584.53,3072.99 R35.1@2584.53,3133.11
  L6-BOT w10: v1(2559.65,3048.11) 2584.53,3072.99 R231.2@2584.53,3133.11
NetR33_2: R33.2 R227.2 U3.12 | length 1006.8
  L1-TOP w10: v1(2284.65,2638.11) 2324.65,2598.11 U3.12@2383.07,2598.11 ; v1(2385,3170) 2432.87,3170 R33.2@2474.65,3128.23
  L6-BOT w10: v1(2284.65,2638.11) 2284.65,2719.65 2355,2790 2355,2920 2370,2935 2385,2935 2425,2975 2425,3010.96 2395.96,3040 2365,3040 2340,3065 2340,3125 v1(2385,3170) 2445,3170 2474.65,3140.35 R227.2@2474.65,3128.23
NetR36_1: R36.1 R38.2 R39.2 R229.1 | length 836.8
  L1-TOP w10: R36.1@2644.65,2767.99 2649.76,2762.87 R38.2@2649.76,2653.11 R39.2@2649.76,2523.11 2744.65,2523.11 v1(2759.65,2508.11)
  L6-BOT w10: R229.1@2539.53,2403.11 2539.53,2550.49 2599.04,2610 2725,2610 2759.65,2575.35 v1(2759.65,2508.11)
NetR40_1: R40.1 U3.8 | length 158.5
  L1-TOP w10: U3.8@2383.07,2398.11 2534.53,2398.11 R40.1@2539.53,2403.11
NetR42_1: R42.1 R43.1 R216.2 R234.2 | length 1528
  L1-TOP w10: R43.1@2534.88,770 2534.88,823.35 2644.65,933.11 R42.1@2644.65,937.99 ; R42.1@2669.53,937.87 R42.1@2669.65,937.99
  L6-BOT w10: v1(1809.65,1083.11) 1939.76,1083.11 R216.2@2009.76,1153.11 2009.76,1060.24 2160,910 2380,910 2390,920 2390,1005 2425,1040 2525,1040 2569.65,995.35 v1(2569.65,858.11) 2644.65,933.11 R234.2@2644.65,937.99
NetR45_2: R45.2 R51.1 U6.2 | length 493.7
  L1-TOP w10: R45.2@2945.12,370 3044.88,370 R51.1@3054.88,380 3054.88,345.12 3080,320 3265,320 3320,375 U6.2@3320,421.57
NetR48_2: R48.2 R226.1 U3.13 | length 901.3
  L1-TOP w10: U3.13@2383.07,2648.11 2444.65,2648.11 v1(2459.65,2633.11) ; v1(2909.65,2513.11) 2939.65,2513.11 2989.65,2463.11 R48.2@3009.53,2463.11
  L6-BOT w10: v1@2459.65,2630.35 v1(2459.65,2633.11) 2479.65,2633.11 2519.76,2673.23 R226.1@2519.76,2763.11 2566.89,2763.11 2585,2745 2695,2745 2715,2725 2715,2665 2785,2595 2827.76,2595 v1(2909.65,2513.11)
NetR49_2: R49.2 U6.12 | length 339.9
  L1-TOP w10: R49.2@3085.12,570 3200,570 3215,555 3345,555 3370,580 U6.12@3370,618.43
NetR50_1: R50.1 R241.2 U6.13 | length 401
  L1-TOP w10: R50.1@3225.12,720 3245.12,740 v1(3340,740) 3320,720 U6.13@3320,618.43
  L6-BOT w10: R241.2@3225.12,660 3260,660 v1(3340,740)
NetR50_2: R50.2 U6.14 | length 220.6
  L1-TOP w10: R50.2@3114.88,720 3114.88,680.12 3176.57,618.43 U6.14@3270,618.43
NetR53_1: R53.1 R243.2 U7.2 | length 538.1
  L1-TOP w10: R53.1@3299.88,2475 3299.88,2405.12 3320,2385 3420,2385 3460,2345 U7.2@3516.57,2345
  L6-BOT w10: R243.2@3299.88,2475 3299.88,2405.12 3330,2375 3430,2375 v1(3440,2365)
NetR56_1: R56.1 R244.2 U7.6 | length 635.2
  L1-TOP w10: R56.1@3249.88,1975 3249.88,2009.88 3315,2075 3385,2075 3455,2145 U7.6@3516.57,2145
  L6-BOT w10: R244.2@3249.88,1975 3249.88,2014.88 3310,2075 3385,2075 v1(3440,2130)
NetR59_1: R59.1 R251.2 U6.9 | length 375.3
  L1-TOP w10: U6.9@3520,618.43 v1(3520,695) 3525,695 3560,730 R59.1@3654.88,730
  L6-BOT w10: v1(3520,695) 3525,695 3560,730 R251.2@3654.88,730
NetR60_1: R60.1 R254.2 U7.13 | length 465.4
  L1-TOP w10: U7.13@3713.43,2345 3770,2345 v1(3790,2365) 3865,2365 3925.12,2425.12 R60.1@3925.12,2460
  L6-BOT w10: v1(3790,2365) 3820.12,2365 R254.2@3930.12,2475
NetR62_1: R62.1 U8.8 | length 136.4
  L1-TOP w10: U8.8@3801.85,1055 3805.12,1051.73 R62.1@3805.12,920
NetR64_1: R64.1 R72.2 U6.6 | length 625.2
  L1-TOP w10: U6.6@3515,416.57 U6.6@3520,421.57 3520,370 3550,340 3585,340 3625,380 R64.1@3654.88,380 3654.88,364.88 R64.1@3635,345 ; 3575,340 3595,320 3860,320 3874.88,334.88 R72.2@3874.88,380
  other v1: 3555,340
NetR65_2: R65.2 U9.5 | length 121.4
  L1-TOP w10: R65.2@3810,2969.88 3820.12,2969.88 3860,2930 U9.5@3860,2875.16
NetR66_2: R66.2 R75.1 U8.13 | length 463.8
  L1-TOP w10: U8.13@3801.85,1305 3885,1305 3910,1330 3935,1330 3955,1350 3955,1390.12 R75.1@4010,1445.12 ; R66.2@3915.12,1560 4010,1465.12 R75.1@4010,1445.12 ; R75.1@3990.12,1445.12 R75.1@4010,1445.12
NetR69_1: R69.1 R257.2 U7.9 | length 661.1
  L1-TOP w10: U7.9@3713.43,2145 3775,2145 v1(3790,2130) 3790,2115 3865,2040 3940,2040 3980.12,1999.88 R69.1@3980.12,1965
  L6-BOT w10: v1(3790,2130) 3790,2115 3865,2040 3945,2040 3980.12,2004.88 R257.2@3980.12,1965
NetR70_1: R70.1 R249.2 U8.9 | length 465.5
  L1-TOP w10: v1(3680.12,999.88) 3720,1039.76 3720,1075 3750,1105 3875,1105 3914.88,1065.12 R70.1@3914.88,1000
  L6-BOT w10: R249.2@3680.12,915 v1(3680.12,999.88)
NetR70_2: R70.2 R71.1 R80.1 R259.2 | length 587.7
  L1-TOP w10: v1(4080,765) 4065,780 R71.1@4015.12,780 4025.12,790 R70.2@4025.12,1000 4124.88,900.24 R80.1@4124.88,840
  L6-BOT w10: R259.2@3995.12,750 4065,750 v1(4080,765)
NetR73_2: R73.2 U9.1 | length 116.3
  L1-TOP w10: R73.2@4020,2974.88 4020,2970 4060,2930 U9.1@4060,2875.16
NetR74_1: R74.1 R79.2 U12.11 | length 872
  L1-TOP w10: R79.2@4235.12,1490 4235.12,1590 R74.1@4215.12,1610 4255,1610 4305,1660 4585,1660 4605,1640 4660,1640 4720,1580 4760,1580 4785,1605 4785,1645 4770,1660 U12.11@4770,1708.43
NetR74_2: R74.2 R88.1 R89.2 U12.13 U15.2 U15.6 | length 1825.6
  L1-TOP w10: R74.2@4104.88,1610 4104.88,1674.88 4133,1703 4353,1703 4429.88,1779.88 R89.2@4490,1779.88 ; R89.2@4499.88,1770 4320,1949.88 4320,2115.96 4344.04,2140 4460,2140 4495.12,2104.88 R88.1@4495.12,2085 4671.57,2085 U15.2@4676.57,2080 ; U12.13@4670,1708.43 4670,1745 4645,1770 4600,1770 4565,1735 4510,1735 4490,1755 4490,1790 4575,1875 4671.57,1875 U15.6@4676.57,1880
NetR77_1: R77.1 U10.12 | length 122.6
  L1-TOP w10: R77.1@4255.12,2550 4260,2550 4320,2610 U10.12@4320,2642.84
NetR78_2: R78.2 U10.7 | length 157.5
  L1-TOP w10: R78.2@4135,2974.88 4170.12,2974.88 4220,2925 U10.7@4220,2873.16
NetR82_1: R82.1 U10.1 | length 132.4
  L1-TOP w10: R82.1@4470,2984.88 4520,2934.88 U10.1@4520,2873.16
NetR83_1: R83.1 R84.2 U11.5 | length 324.1
  L1-TOP w10: R83.1@4250,1245 R84.2@4250,1135.24 4310.12,1135.24 4365,1190.12 U11.5@4441.57,1190.12
NetR83_2: R83.2 R266.1 R271.2 U11.2 U11.6 U11.14 | length 1737.2
  L1-TOP w10: v1(4320,1460) 4250,1390 R83.2@4250,1355.24 4426.46,1355.24 U11.2@4441.57,1340.12 4475,1340.12 4525,1390.12 U11.14@4638.43,1390.12 ; v1(4345,910.12) 4345,1070.12 U11.6@4415,1140.12
  L6-BOT w10: v1(4320,1460) 4250,1390 R266.1@4250,1135.24 4185,1070.24 4185,975 4210,950 4305.12,950 v1(4345,910.12) 4345,970.12 R271.2@4444.88,1070
NetR85_1: R85.1 U10.14 | length 115.7
  L1-TOP w10: R85.1@4364.88,2550 4420,2605.12 U10.14@4420,2642.84
NetR86_1: R86.1 R87.2 U14.5 | length 401.4
  L1-TOP w10: R87.2@4374.88,2275 4374.88,2314.88 4390,2330 4465,2330 4485.12,2350.12 R86.1@4485.12,2390 4485.24,2389.88 4570.12,2389.88 4595,2365 U14.5@4671.57,2365
NetR86_2: R86.2 R267.2 R276.1 U14.1 U14.2 U14.10 | length 1311.2
  L1-TOP w10: R86.2@4374.88,2390 4374.88,2439.88 4395,2460 4520,2460 4560,2500 v1(4585,2500) 4600,2515 U14.2@4671.57,2515 U14.1@4671.57,2565 ; U14.1@4666.69,2560.12 U14.1@4671.57,2565 ; v1(4770,2535) 4740,2565 U14.1@4671.57,2565 ; U14.10@4868.43,2365 4920,2365 v1(4955,2330)
  L3-Signal w10: v1(4770,2535) 4855,2450 4855,2430 v1(4955,2330)
  L6-BOT w10: R267.2@4374.88,2390 4374.88,2439.88 4395,2460 4525,2460 4565,2500 v1(4585,2500) ; v1(4770,2535) 4839.88,2535 R276.1@4844.88,2530 ; R276.1@4829.88,2535 R276.1@4844.88,2520
NetR89_1: R89.1 R269.2 U15.5 | length 311.5
  L1-TOP w10: R89.1@4514.88,1915 R89.1@4490,1890.12 4535.12,1890.12 4575,1930 U15.5@4676.57,1930
  L6-BOT w10: R269.2@4490,1890.12 4535.12,1890.12 v1(4555,1910)
NetR90_1: R90.1 R96.2 R265.2 U12.1 U12.2 U12.8 | length 1707.4
  L1-TOP w10: R90.1@4455.12,1560 4571.57,1560 U12.1@4620,1511.57 ; v1(4585,1450) 4585,1455 4620,1490 U12.1@4620,1511.57 ; U12.8@4920,1708.43 4920,1770 4970,1820 5085,1820 5098,1807 5098,1743 5085,1730 5085,1430 4990,1335 4799.88,1335 R96.2@4744.88,1390 4730,1390 4670,1450 U12.2@4670,1511.57 U12.1@4620,1511.57
  L6-BOT w10: R265.2@4525.12,1610 4525.12,1509.88 v1(4585,1450)
NetR91_2: R91.2 R94.1 U16.5 | length 322.9
  L1-TOP w10: R91.2@4440,785.12 4655.12,785.12 4680,810 U16.5@4731.57,810 ; 4695.12,795.12 U16.5@4710,810
NetR92_2: R92.2 R271.1 U11.9 | length 526.4
  L1-TOP w10: v1(4470,910) 4555.12,995.12 4555.12,1045.24 4580,1070.12 4580,1120.12 4600,1140.12 U11.9@4638.43,1140.12
  L6-BOT w10: v1(4470,910) 4485,910 4555.12,980.12 R271.1@4555.12,1070
NetR93_1: R93.1 U13.7 | length 125.4
  L1-TOP w10: R93.1@4660,3014.88 4710,2964.88 U13.7@4710,2910.16
NetR94_2: R94.2 R98.2 R99.1 U16.2 U16.6 U16.13 | length 1382.6
  L1-TOP w10: U16.2@4731.57,960 4775,960 ; R99.1@4850,565.12 4619.88,565.12 4560,625 R94.2@4560,674.88 4564.88,674.88 4650,760 4770,760 4790,780 4790,945 4775,960 ; U16.13@4970,960 4995,985 4995,1089.88 R98.2@4930,1154.88 4889.88,1154.88 4830,1095 4830,1015 4775,960
NetR95_1: R95.1 U13.5 | length 121.3
  L1-TOP w10: U13.5@4810,2910.16 4810,2974.88 R95.1@4850,3014.88
NetR96_1: R96.1 R281.2 U12.5 | length 724.9
  L1-TOP w10: U12.5@4820,1511.57 4820,1450 4855.12,1414.88 R96.1@4855.12,1390 5015,1390 5065,1440 5065,1665 5045,1685 v1(5010,1685)
  L6-BOT w10: R281.2@5010,1615.12 v1(5010,1685)
NetR97_1: R97.1 R104.2 U15.9 | length 501.1
  L1-TOP w10: U15.9@4873.43,1880 v1(4965,1880) 4970.12,1874.88 R97.1@5050,1874.88 ; v1(4990,2055) 5024.88,2089.88 R104.2@5070,2089.88 ; R97.1@5039.88,1880 R97.1@5070,1849.88
  L6-BOT w10: v1(4965,1880) 4990,1905 v1(4990,2055)
NetR97_2: R97.2 R103.2 R283.1 U14.14 U15.10 U15.14 | length 1466.5
  L1-TOP w10: U14.14@4868.43,2565 4925,2565 4955,2535 4955,2500 5030,2425 R103.2@5030,2415.12 5089.88,2415.12 5120,2385 5120,2005 5100.12,1985.12 5030.12,1985.12 4980,1935 4878.43,1935 U15.10@4873.43,1930 ; U15.14@4873.43,2130 4965,2130 v1(4970,2135) 4970,2115 4945,2090 4945,1995 4979.88,1960.12 5005.12,1960.12
  L6-BOT w10: v1(4970,2135) 5025.12,2190.12 5025.12,2200.12 R283.1@5070,2200.12
NetR98_1: R98.1 R100.2 U16.11 | length 847.7
  L1-TOP w10: U16.11@4928.43,860 4985,860 ; R98.1@4930,1265.12 5020,1175.12 5020,895 4985,860 ; R100.2@4970,565.12 5025,620.12 5025,820 4985,860
NetR101_1: R101.1 U13.3 | length 193.8
  L1-TOP w10: U13.3@4910,2910.16 4910,2945 4979.88,3014.88 R101.1@5040,3014.88
NetR102_2: R102.2 R265.1 U12.7 | length 997.2
  L1-TOP w10: U12.7@4915,1516.57 U12.7@4920,1511.57 v1(4920,1595) ; U12.7@4920,1511.57 4926.69,1504.88 R102.2@5010,1504.88
  L6-BOT w10: R265.1@4414.88,1610 4414.88,1515.12 4520,1410 4895,1410 4920,1435 v1(4920,1595)
NetR103_1: R103.1 R282.2 U14.9 | length 645.3
  L1-TOP w10: v1(4765,2275) 4770,2275 4810,2315 4915,2315 4940,2290 5015.12,2290 R103.1@5030,2304.88
  L6-BOT w10: v1(4765,2275) 4765,2280 4835,2350 4915,2350 4940,2375 4975,2375 5000,2350 5000,2334.88 R282.2@5030,2304.88
NetR105_1: R105.1 U17.1 | length 95.9
  L1-TOP w10: U17.1@5095,1114.84 5095,1040.12 R105.1@5110,1025.12
NetR106_1: R106.1 R115.2 R289.2 U20.1 U20.2 U20.8 | length 1499.2
  L1-TOP w10: R106.1@5150,795.12 5189.88,795.12 5225,760 U20.1@5261.57,760 U20.2@5261.57,710 ; U20.1@5260,760 5260,800 v1(5235,825) 5265,825 5300,790 5530,790 5553,767 5553,597 5685,465 5685,360 5665,340 5505.12,340 R115.2@5475.12,370 ; U20.8@5458.43,460 5475.12,443.31 R115.2@5475.12,370 ; R115.2@5490,370 R115.2@5475.12,370
  L6-BOT w10: v1(5235,825) 5275.12,865.12 R289.2@5275.12,910
NetR107_2: R107.2 R289.1 U20.5 | length 500.9
  L1-TOP w10: R107.2@5150,515.12 5194.88,560 U20.5@5261.57,560 ; v1(5170,605) 5215,560
  L6-BOT w10: R289.1@5164.88,910 5164.88,610.12 v1(5170,605)
NetR108_1: R108.1 U13.1 | length 263.4
  L1-TOP w10: U13.1@5010,2910.16 5125.28,2910.16 R108.1@5230,3014.88
NetR109_2: R109.2 U9.14 | length 2636.3
  L1-TOP w10: U9.14@3960,2644.84 v1(3960,2765) ; R109.2@5315.12,1530 5325,1539.88 v1(5325,1605)
  L3-Signal w10: v1(5245,2130) 5245,2125 5280,2090 5280,1715 5325,1670 v1(5325,1605)
  L6-BOT w10: v1(3960,2765) 3940,2765 3915,2740 3915,2635 3935,2615 4575,2615 4590,2630 5030,2630 5185,2475 5185,2190 v1(5245,2130)
NetR110_1: R110.1 U17.5 | length 101.8
  L1-TOP w10: R110.1@5290,1015.12 5295,1020.12 U17.5@5295,1114.84
NetR111_1: R111.1 U18.7 | length 134.2
  L1-TOP w10: U18.7@5285,2615.16 5285,2699.88 R111.1@5320,2734.88
NetR112_1: R112.1 U18.3 | length 598.6
  L1-TOP w10: R112.1@5420,2984.88 5464.88,2940 5580,2940 5605,2915 5605,2700 5573,2668 5513,2668 5485,2640 U18.3@5485,2615.16
NetR114_2: R114.2 U17.7 | length 105.9
  L1-TOP w10: U17.7@5395,1114.84 5395,1065 5410,1050 R114.2@5410,1015.12
NetR115_1: R115.1 R293.2 U20.7 | length 348.3
  L1-TOP w10: v1@5242.5,412.5 5261.57,431.57 U20.7@5261.57,460 ; v1@5245,410 v1(5240,410) 5280,370 R115.1@5364.88,370
  L6-BOT w10: v1(5240,410) 5280,370 R293.2@5369.88,370
NetR116_1: R116.1 U18.5 | length 203.8
  L1-TOP w10: U18.5@5385,2615.16 5385,2665 5454.88,2734.88 R116.1@5510,2734.88
NetR118_1: R118.1 U18.1 | length 442.7
  L1-TOP w10: R118.1@5570,2984.88 5610.12,2984.88 5630,2965 5630,2650 5595.16,2615.16 U18.1@5585,2615.16
NetR119_1: R119.1 U21.3 | length 213.8
  L1-TOP w10: R119.1@5610,935 5610,1020 5675,1085 U21.3@5675,1114.84 U21.3@5680,1109.84
NetR120_1: R120.1 U21.7 | length 530.8
  L1-TOP w10: R120.1@5640.12,725.24 5715,800.12 5715,995 5785,1065 5860,1065 5875,1080 U21.7@5875,1114.84
NetR121_1: R121.1 U22.5 | length 430.8
  L1-TOP w10: R121.1@5760,685.12 5760,750 5735,775 5735,845 5750,860 5900,860 5935,825 U22.5@5974.84,825
NetR122_1: R122.1 U22.1 | length 322.3
  L1-TOP w10: R122.1@5815.12,915.12 R122.1@5800,915.12 5800,1035 5810,1045 5954.84,1045 U22.1@5974.84,1025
